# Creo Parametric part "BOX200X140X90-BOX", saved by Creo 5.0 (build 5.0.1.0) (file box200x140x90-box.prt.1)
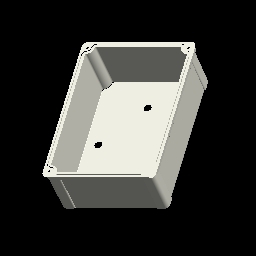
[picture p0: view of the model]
Units: millimeter Kilogram Sec (mmKs); MM, KILOGRAM, SECS
Materials in the file: PP, ABS

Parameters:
  PTC_MATERIAL_NAME = "ABS"

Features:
  1. coordinate system "BOX200X140X90-BOX"
  2. imported feature "Función De Importación ID 5"
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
